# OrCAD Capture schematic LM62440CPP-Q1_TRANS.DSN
size D; title: LM62440CPP-Q1 Automotive 3-V to 36-V, 4-A, Low EMI; rev: 1.0; note: Datasheet:SNVSAW8B       EVM:SNVU622; note: Synchronous Step-Down Converter
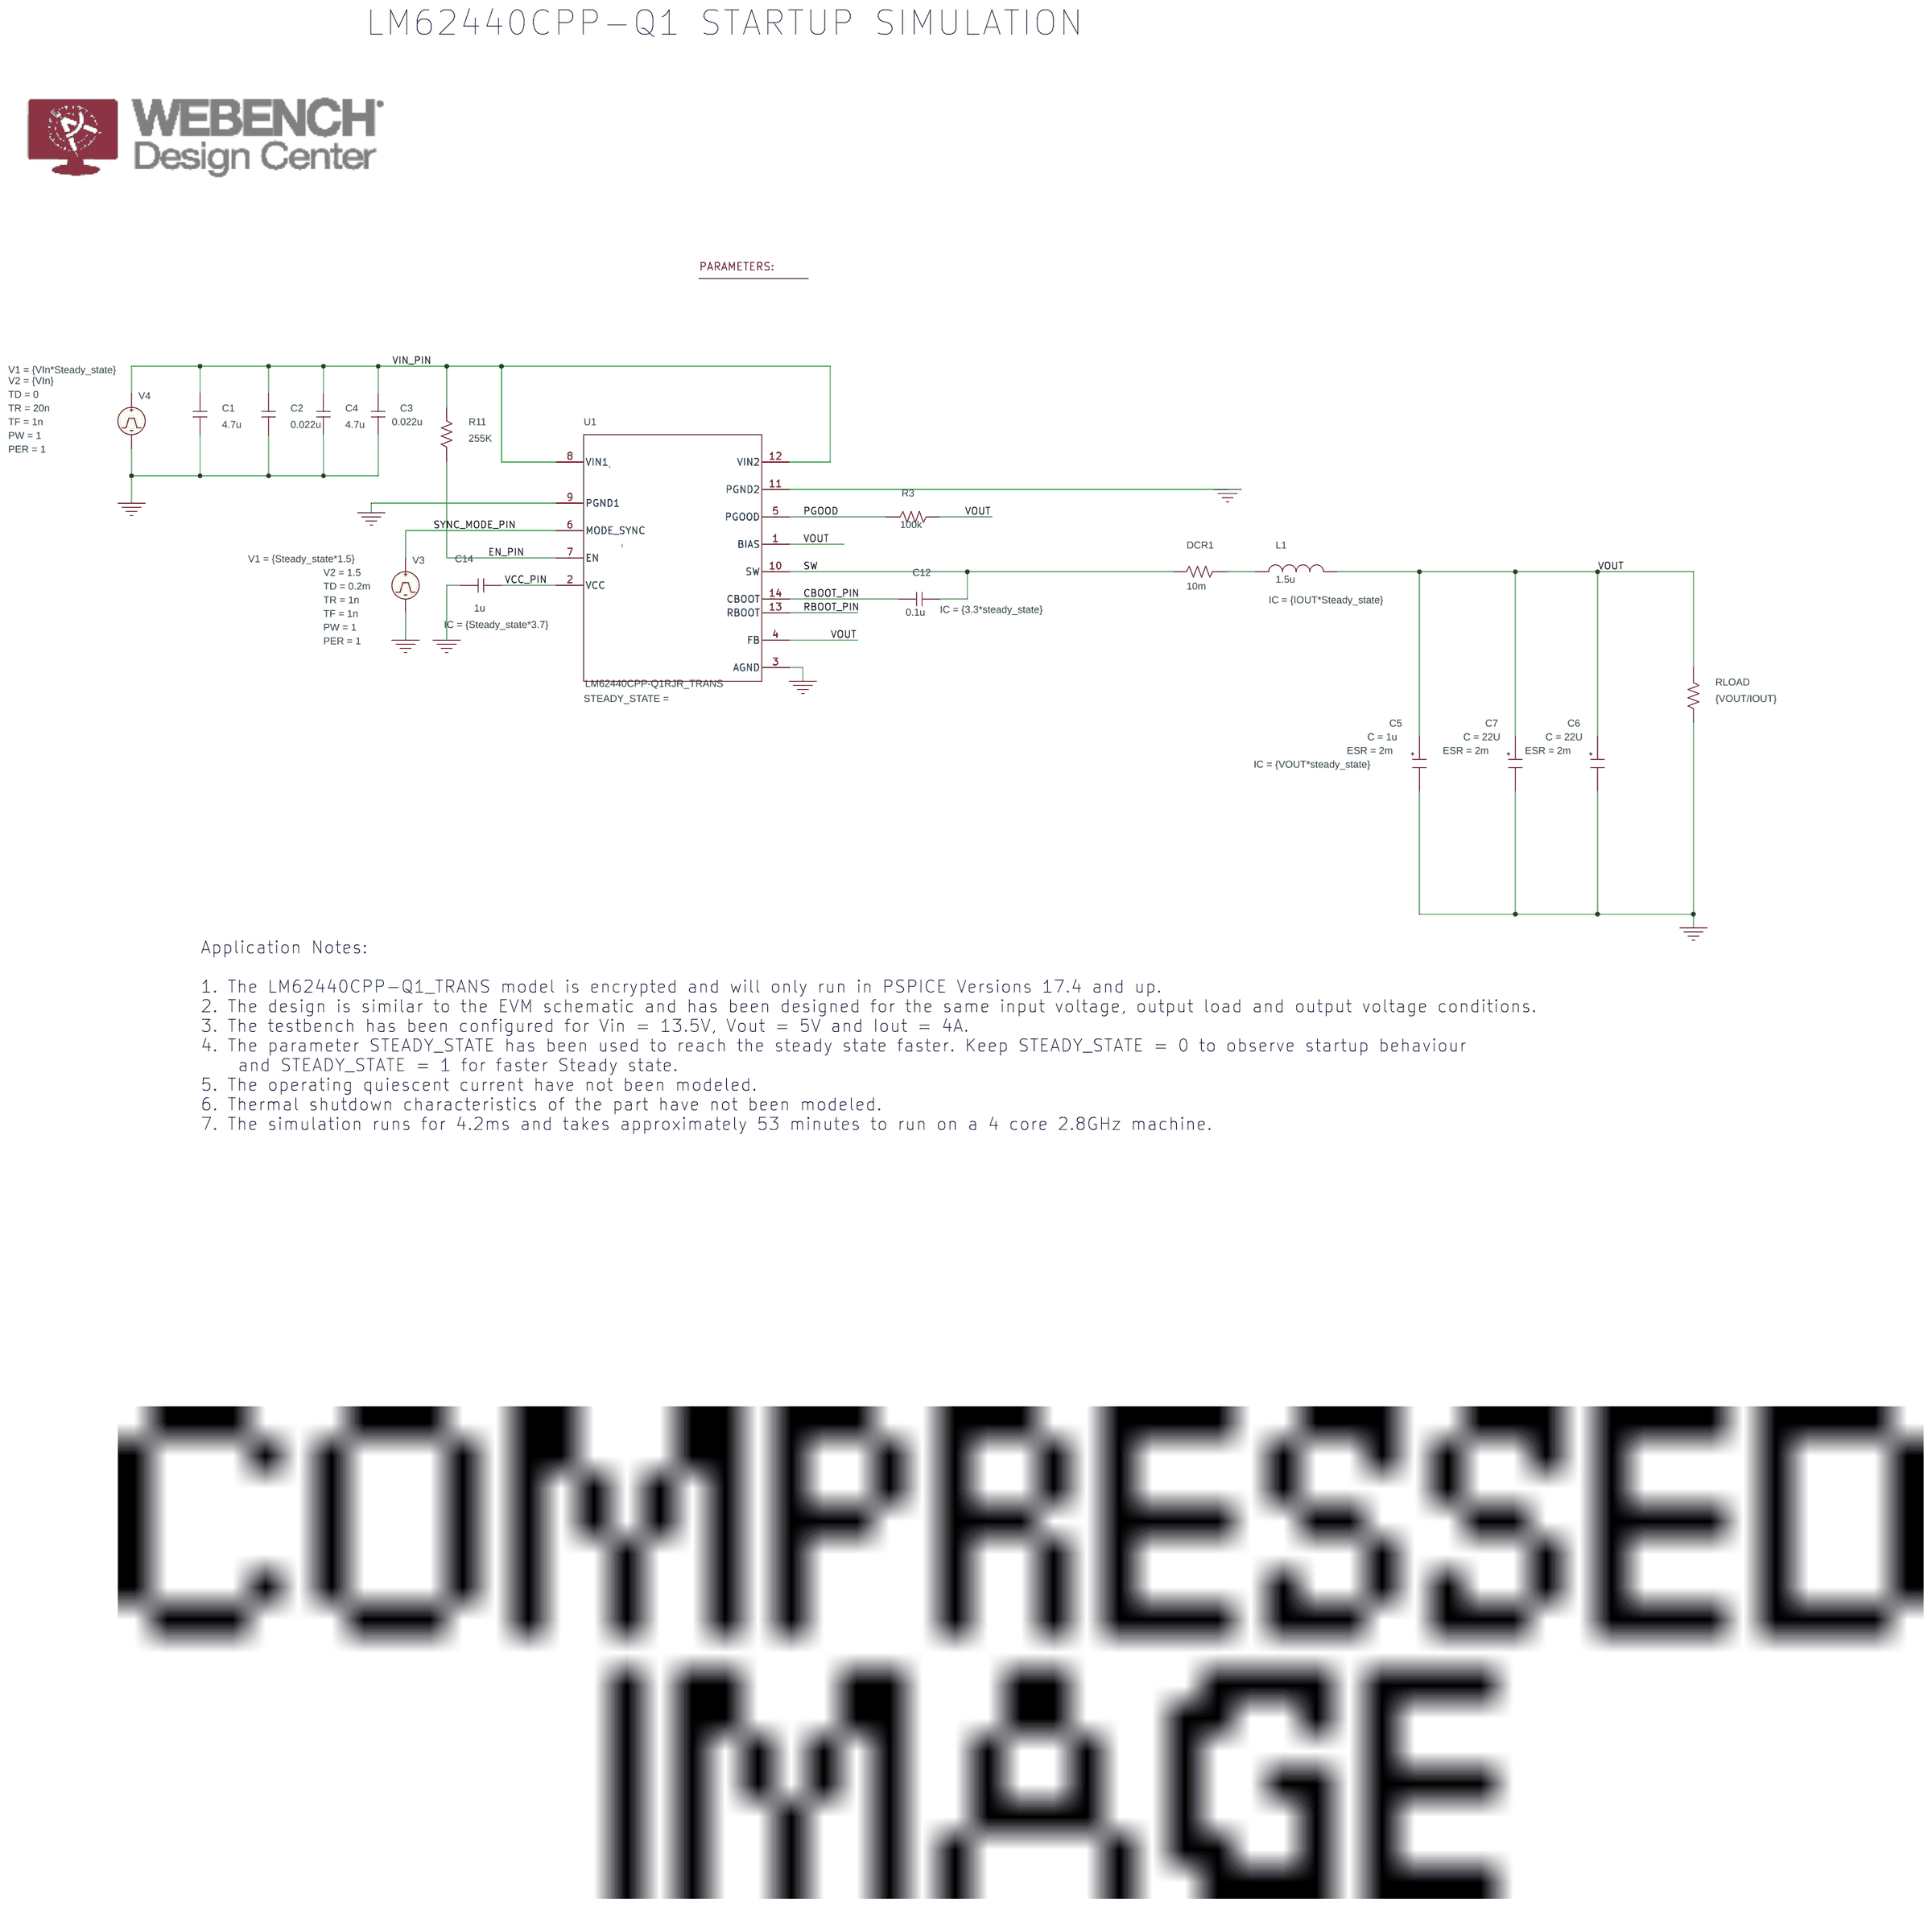
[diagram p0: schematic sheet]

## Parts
1  PARAM
C1  4.7u  [RAD/CK05]
C2  0.022u  [RAD/CK05]
C3  0.022u  [RAD/CK05]
C4  4.7u  [RAD/CK05]
C5  CESR
C6  CESR
C7  CESR
C12  0.1u  [RAD/CK05]
C14  1u  [RAD/CK05]
DCR1  10m  [AX/RC05]
L1  1.5u  [DISC/.350x.175/LS.200x.100/.034]
R3  100k  [AX/RC05]
R11  255K  [AX/RC05]
RLOAD  {VOUT/IOUT}  [AX/RC05]
U1  LM62440CPP-Q1RJR_TRANS  [RJR0014A-MFG]
V3  VPULSE
V4  VPULSE

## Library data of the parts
1 = PARAM: Iout: 4; STEADY_STATE: 0; VIn: 13.5; Vout: 5
C1-C4 = C
C5 = CESR_0: C: 1u; ESR: 2m; IC: {VOUT*steady_state}; PSpiceTemplate: X^@REFDES %IN %OUT @MODEL PARAMS:  ?C|C=@C||C=100u|  ?ESR|ESR=@ESR||ESR=0.01| ?X|X=@X||X=2|  ?IC|IC=@IC||IC=2|; X: 1
C6 C7 = CESR_0: C: 22U; ESR: 2m; IC: {VOUT*steady_state}; PSpiceTemplate: X^@REFDES %IN %OUT @MODEL PARAMS:  ?C|C=@C||C=100u|  ?ESR|ESR=@ESR||ESR=0.01| ?X|X=@X||X=2|  ?IC|IC=@IC||IC=2|; X: 1
C12 = C: IC: {3.3*steady_state}
C14 = C: IC: {Steady_state*3.7}
DCR1 R3 R11 RLOAD = R
L1 = L: IC: {IOUT*Steady_state}
U1 = LM62440CPP-Q1RJR_TRANS
V3 = VPULSE: PER: 1; PW: 1; TD: 0.2m; TF: 1n; TR: 1n; V1: {Steady_state*1.5}; V2: 1.5
V4 = VPULSE: PER: 1; PW: 1; TD: 0; TF: 1n; TR: 20n; V1: {VIn*Steady_state}; V2: {VIn}

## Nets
VCC_PIN: C14.1 U1.2(VCC)
VIN_PIN: C1.1 C2.1 C3.1 C4.1 R11.2 U1.8(VIN1) U1.12(VIN2) V4.1(+)
0: C1.2 C2.2 C3.2 C4.2 C5.2(OUT) C6.2(OUT) C7.2(OUT) C14.2 RLOAD.2 U1.3(AGND) U1.9(PGND1) U1.11(PGND2) V3.2(-) V4.2(-)
CBOOT_PIN: C12.1 U1.14(CBOOT)
EN_PIN: R11.1 U1.7(EN)
PGOOD: R3.1 U1.5(PGOOD)
RBOOT_PIN: U1.13(RBOOT)
SW: C12.2 DCR1.2 U1.10(SW)
SYNC_MODE_PIN: U1.6(MODE_SYNC) V3.1(+)
VOUT: C5.1(IN) C6.1(IN) C7.1(IN) L1.2 R3.2 RLOAD.1 U1.1(BIAS) U1.4(FB)
N16770929: DCR1.1 L1.1

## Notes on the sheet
- LM62440CPP-Q1 STARTUP SIMULATION
- Application Notes:
  1. The LM62440CPP-Q1_TRANS model is encrypted and will only run in PSPICE Versions 17.4 and up.
  2. The design is similar to the EVM schematic and has been designed for the same input voltage, output load and output voltage conditions.
  3. The testbench has been configured for Vin = 13.5V, Vout = 5V and Iout = 4A.
  4. The parameter STEADY_STATE has been used to reach the steady state faster. Keep STEADY_STATE = 0 to observe startup behaviour
      and STEADY_STATE = 1 for faster Steady state.
  5. The operating quiescent current have not been modeled.
  6. Thermal shutdown characteristics of the part have not been modeled.
  7. The simulation runs for 4.2ms and takes approximately 53 minutes to run on a 4 core 2.8GHz machine.
